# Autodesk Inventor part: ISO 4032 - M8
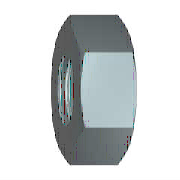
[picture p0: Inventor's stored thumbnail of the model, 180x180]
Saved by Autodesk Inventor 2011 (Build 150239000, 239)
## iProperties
Created: 2009-02
Part Number: ISO 4032 - M8
Material: Stainless Steel, 440C
Description: Hexagon nuts, style 1 - Product grades A and B
Document SubType Name: Modeling
Standard: ISO 4032
Designer: 114149
Standard Revision: Third edition 1999-08-15
Standards Organization: ISO
Language: en-US
Size Designation: M8
Categories: <MemberInstance><Categories><Category DisplayName="Fasteners" InternalName="e4da775c-781d-43d5-af7c-5136215cf5a6" Mnemonic="FSTN"><Category DisplayName="Nuts" I
Density: 7.75 g/cm^3
Mass: 5.63 g
Surface Area: 6.18308 cm^2
Volume: 0.726452 cm^3
IsCustomPart: 0
Author: 114149
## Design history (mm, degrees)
body "Solid1"
workaxis "Work Axis1"
workplane "Work Plane1"
sketch "Sketch1"
  geometry: L1 (-7.506, 0)-(-3.753, 6.5); L2 (-3.753, 6.5)-(3.753, 6.5); L3 (3.753, 6.5)-(7.506, 0); L4 (7.506, 0)-(3.753, -6.5); L5 (3.753, -6.5)-(-3.753, -6.5); L6 (-3.753, -6.5)-(-7.506, 0); 2 further points
  constraints: 12 end point, 1 coincident, 1 horizontal, 11 other
  dimensions: "d0" = 15.01111 distance of L3.end L1.start (= 1.1547 x SW)
extrude "Body" new body sketch "Sketch1" distance "d1" = 6.8 (= KOH); taper "d2" = 0 deg
revolve "Chamfer1" stored, may be unused: angle "d7" = 90 deg
sketch "Sketch3"
  geometry: 4 further points
  constraints: 1 coincident, 1 other
hole "Thread" sketch "Sketch3" diameter "d25" = 6.647; stored, may be unused: countersink angle "d29" = 82 deg, drill point angle "d31" = 118 deg; dims "d26" = 6, "d27" = 4, "d28" = 2, "d30" = 8
chamfer "Chamfer2" distance "d8" = 0.67658 (= -0.5 x GD1 + 0.5 x NND); stored, may be unused: angle "d9" = 30 deg, second distance "d40" = 0.67658 (= -0.5 x GD1 + 0.5 x NND)
chamfer "Chamfer3" distance "d10" = 0.67658 (= -0.5 x GD1 + 0.5 x NND); stored, may be unused: angle "d11" = 30 deg, second distance "d41" = 0.67658 (= -0.5 x GD1 + 0.5 x NND)
sketch "Sketch2"
  geometry: L1 (0, 3.753)-(0, 7.506) reference; L2 (0, 7.506)-(6.8, 7.506) reference; L3 (6.8, 3.753)-(6.8, 7.506) reference; L4 (-1.36, 0)-(8.16, 0) reference; L5 (0.985, 7.506)-(0, 5.8); L6 (5.815, 7.506)-(6.8, 5.8)
  constraints: 4 end point, 4 point on line
  dimensions: "d3" = 30 deg angle of L1 L5 (= ANG1); "d4" = 30 deg angle of L3 L6 (= ANG2); "d5" = 11.6 diameter of L5.end L4 (= SW0); "d6" = 11.6 diameter of L6.end L4 (= SW01)
other parameters: "ANG1" = 30 deg [user parameter; used in 1 equation term], "ANG2" = 30 deg [user parameter; used in 1 equation term], "NND" = 8 [user parameter; used in 4 equation terms], "KOH" = 6.8 [user parameter; used in 1 equation term], "SW" = 13 [user parameter; used in 2 equation terms], "SW0" = 11.6 [user parameter; used in 2 equation terms], "SW01" = 11.6 (= SW0) [user parameter; used in 1 equation term], "GD1" = 6.64684 (computed from THREADDIA, PTC, TOA) [user parameter; used in 4 equation terms], "d13" = 0, "d14" = 0, "d39" = 0, "d42" = 0, "GUL" = 0.67658 (= 0.541266 x PTC) [user parameter], "TPU" = 8 (computed from PTC) [user parameter], "THREADDIA" = 8 [user parameter; used in 1 equation term], "TOA" = 30 deg [user parameter; used in 1 equation term], "PTC" = 1.25 [user parameter; used in 4 equation terms], "E0" = 15.015 (= 1.155 x SW) [user parameter], "GAL" = 0.67658 (= 0.541266 x PTC) [user parameter]
